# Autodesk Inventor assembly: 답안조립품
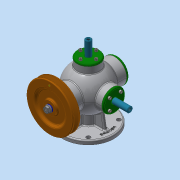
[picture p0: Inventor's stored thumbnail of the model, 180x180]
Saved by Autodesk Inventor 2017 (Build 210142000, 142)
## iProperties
Part Number: 답안조립품
Material: 일반
Document SubType Name: Assembly
Designer: MRC
Mass: 3778.23 g
Surface Area: 2410.88 cm^2
Volume: 904.616 cm^3
Density: 4.17662 g/cm^3
Author: MRC
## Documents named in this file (17)
- C:\Users\MRC\Desktop\600911V1006\답안조립품.iam
- C:\Users\MRC\Desktop\600911V1006\본체.ipt
- C:\Users\MRC\Desktop\600911V1006\V-벨트풀리.ipt
- C:\Users\MRC\Desktop\600911V1006\너트 M8x1.ipt
- C:\Users\MRC\Desktop\600911V1006\뒤커버.ipt
- C:\Users\MRC\Desktop\600911V1006\베어링 6202.ipt
- C:\Users\MRC\Desktop\600911V1006\본체커버.ipt
- C:\Users\MRC\Desktop\600911V1006\볼트 M4.ipt
- C:\Users\MRC\Desktop\600911V1006\스프링1.ipt
- C:\Users\MRC\Desktop\600911V1006\스프링2.ipt
- C:\Users\MRC\Desktop\600911V1006\슬라이드 커버.ipt
- C:\Users\MRC\Desktop\600911V1006\슬라이드.ipt
- C:\Users\MRC\Desktop\600911V1006\앞커버.ipt
- C:\Users\MRC\Desktop\600911V1006\오일 실.ipt
- C:\Users\MRC\Desktop\600911V1006\와셔 8x17.ipt
- C:\Users\MRC\Desktop\600911V1006\축.ipt
- C:\Users\MRC\Desktop\600911V1006\키 4x4.ipt
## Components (1 placed, 1 different names)
1. V-벨트풀리:1
